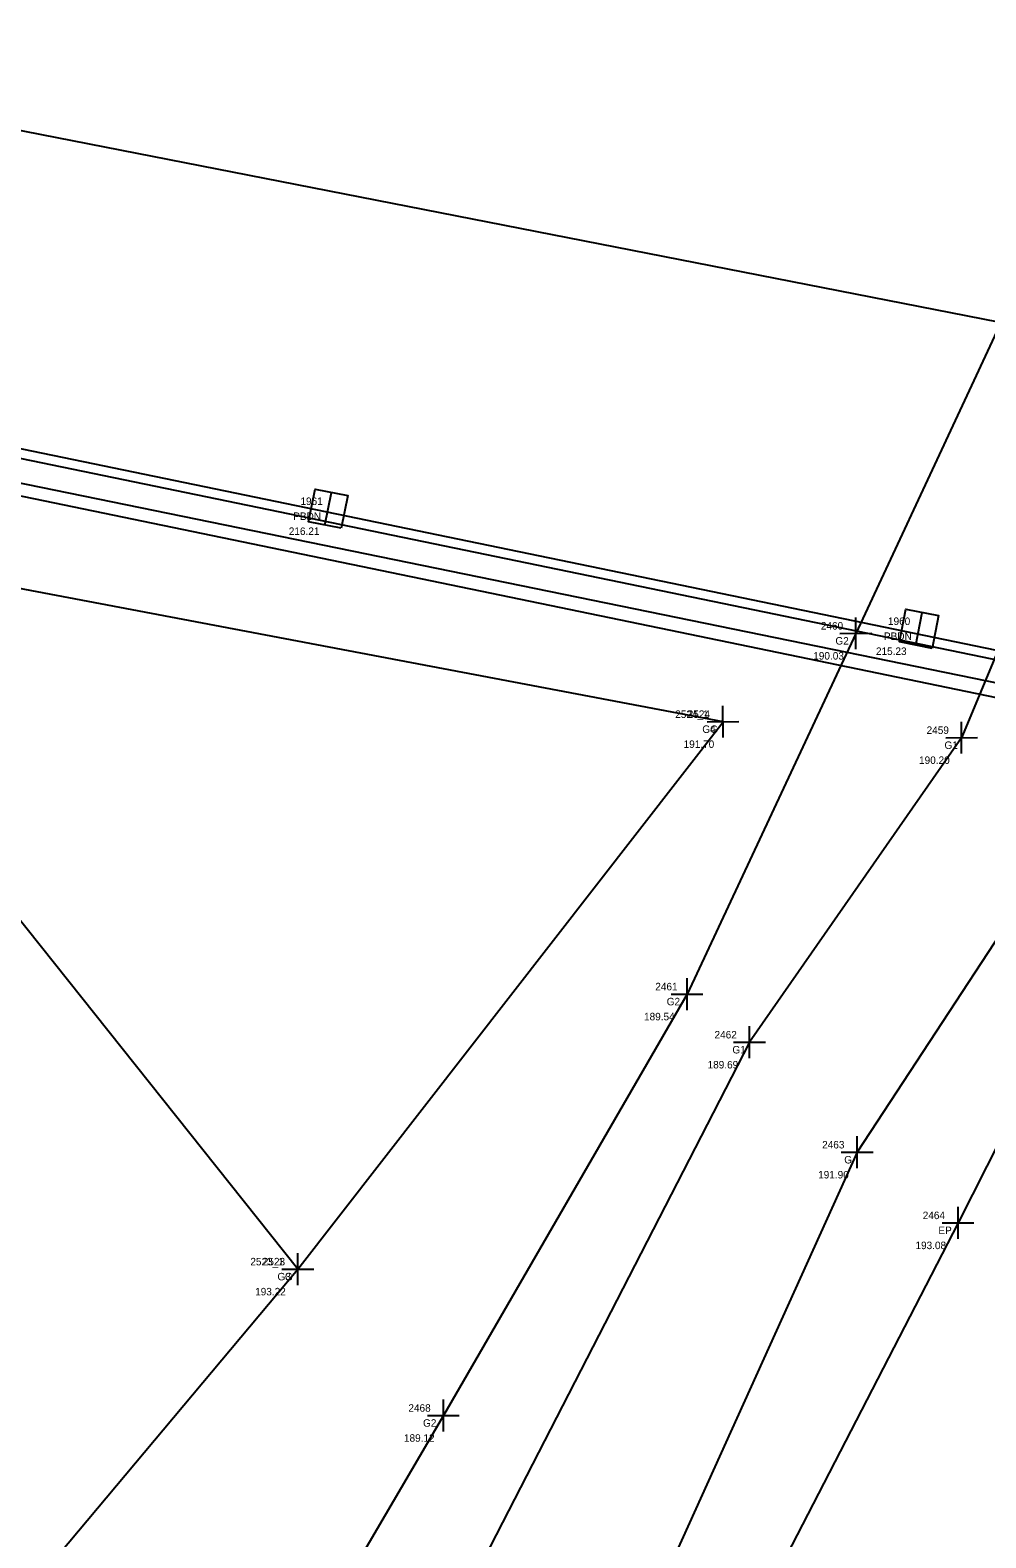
# Model space of a CAD drawing. Extents: x 1155460 to 1157069, y 590691 to 591363.
# Drawn here: x 1156326 to 1156364.2, y 591043.1 to 591103.4 of the extents above; entities that cross this region are included whole.
import ezdxf

# ---------------------------------------------------------------- set-up
doc = ezdxf.new("R2010")
doc.units = 0
for name, color, linetype in [('Default', 7, 'Continuous'), ('S_Bridge_Centerline', 7, 'Continuous'), ('S_Bridge_Curb', 7, 'Continuous'), ('S_Bridge_Deck', 7, 'Continuous'), ('S_Bridge_Downspout', 7, 'Continuous'), ('S_Bridge_Rail', 7, 'Continuous'), ('S_Field_Code', 7, 'Continuous'), ('S_Ground_Elevation', 7, 'Continuous'), ('S_Point_Elevation', 7, 'Continuous'), ('S_Point_Name', 7, 'Continuous'), ('S_Roadway_Edge_Pavement', 7, 'Continuous'), ('S_Survey_Shot', 7, 'Continuous')]:
    doc.layers.add(name, color=color, linetype=linetype)

msp = doc.modelspace()

# ---------------------------------------------------------------- linework, layer by layer
at = {"layer": 'Default'}
for p, q in [((1156337.9, 591084.266), (1156337.9, 591084.266)), ((1156361.542, 591079.466), (1156361.542, 591079.466))]:
    msp.add_line(p, q, dxfattribs=at)
at = {"layer": 'S_Bridge_Centerline'}
msp.add_lwpolyline([(1156315.508, 591101.371), (1156372.408, 591090.24), (1156431.554, 591078.114), (1156475.254, 591069.515)], dxfattribs=at)
at = {"layer": 'S_Bridge_Curb'}
for points in [[(1156309.461, 591089.603), (1156368.986, 591077.329), (1156424.735, 591065.932), (1156469.272, 591056.957)], [(1156468.917, 591055.972), (1156425.26, 591064.917), (1156366.557, 591076.907), (1156308.862, 591088.698)]]:
    msp.add_lwpolyline(points, dxfattribs=at)
at = {"layer": 'S_Bridge_Deck'}
msp.add_lwpolyline([(1156321.636, 591113.83), (1156379.075, 591102.191), (1156438.058, 591090.105), (1156481.699, 591081.221), (1156469.523, 591057.135), (1156425.816, 591065.905), (1156367.048, 591078.105), (1156309.431, 591089.995)], close=True, dxfattribs=at)
at = {"layer": 'S_Bridge_Downspout'}
for p, q in [((1156337.769, 591083.612), (1156338.031, 591084.92)), ((1156361.411, 591078.812), (1156361.672, 591080.119))]:
    msp.add_line(p, q, dxfattribs=at)
for points in [[(1156338.423, 591083.482), (1156337.116, 591083.743), (1156337.377, 591085.05), (1156338.684, 591084.789)], [(1156362.065, 591078.681), (1156360.757, 591078.942), (1156361.019, 591080.25), (1156362.326, 591079.989)]]:
    msp.add_lwpolyline(points, close=True, dxfattribs=at)
at = {"layer": 'S_Bridge_Rail'}
msp.add_lwpolyline([(1156468.705, 591055.401), (1156424.96, 591064.338), (1156366.256, 591076.365), (1156308.616, 591088.276)], dxfattribs=at)
at = {"layer": 'S_Ground_Elevation'}
for points in [[(1156379.906, 591125.75), (1156371.781, 591106.643), (1156359.013, 591079.281), (1156352.261, 591064.852), (1156342.509, 591047.996), (1156330.29, 591027.131), (1156317.384, 591002.477), (1156294.819, 590961.074), (1156271.751, 590921.229), (1156243.933, 590875.1), (1156220.497, 590838.098), (1156207.923, 590811.33), (1156193.803, 590789.379), (1156193.142, 590778.687)], [(1156384.307, 591123.72), (1156373.986, 591100.844), (1156363.249, 591075.107), (1156354.761, 591062.927), (1156343.414, 591040.885), (1156332.061, 591024.769), (1156321.368, 591002.613), (1156298.102, 590959.872), (1156275.04, 590917.944), (1156250.506, 590874.056), (1156227.624, 590835.562), (1156214.155, 590811.849), (1156201.099, 590789.179), (1156193.142, 590778.687), (1156176.179, 590756.924), (1156172.203, 590742.083)], [(1156390.175, 591120.033), (1156381.064, 591097.503), (1156368.236, 591072.501), (1156359.068, 591058.527), (1156343.042, 591023.13), (1156324.748, 590989.953), (1156305.968, 590954.129), (1156282.703, 590914.702), (1156259.469, 590868.947), (1156237.124, 590831.411), (1156221.354, 590804.624), (1156218.597, 590799.82), (1156211.828, 590795.443), (1156202.716, 590779.447), (1156183.916, 590752.585), (1156173.73, 590734.078)], [(1156353.701, 591075.748), (1156312.515, 591083.537), (1156308.901, 591085.521)], [(1156336.683, 591053.85), (1156319.901, 591074.903), (1156305.515, 591083.097), (1156299.714, 591084.96)], [(1156326.731, 591041.979), (1156336.683, 591053.85), (1156353.701, 591075.748)]]:
    msp.add_lwpolyline(points, dxfattribs=at)
at = {"layer": 'S_Roadway_Edge_Pavement'}
msp.add_lwpolyline([(1156394.452, 591118.152), (1156383.412, 591096.564), (1156371.167, 591071.625), (1156363.107, 591055.7), (1156344.853, 591020.331), (1156327.93, 590987.905), (1156310.138, 590952.311), (1156288.382, 590911.132), (1156264.007, 590866.376), (1156251.804, 590843.99), (1156242.045, 590830.497), (1156229.687, 590815.055), (1156224.596, 590802.999), (1156214.609, 590779.786), (1156200.016, 590742.951), (1156189.63, 590722.324)], dxfattribs=at)
at = {"layer": 'S_Survey_Shot'}
for p, q in [((1156359.015, 591078.645), (1156359.012, 591079.918)), ((1156358.377, 591079.28), (1156359.65, 591079.283)), ((1156359.013, 591079.281), (1156359.013, 591079.281)), ((1156353.702, 591075.112), (1156353.699, 591076.384)), ((1156353.702, 591075.112), (1156353.699, 591076.384)), ((1156353.064, 591075.747), (1156354.337, 591075.749)), ((1156353.064, 591075.747), (1156354.337, 591075.749)), ((1156353.701, 591075.748), (1156353.701, 591075.748)), ((1156353.701, 591075.748), (1156353.701, 591075.748)), ((1156363.25, 591074.471), (1156363.247, 591075.743)), ((1156362.612, 591075.106), (1156363.885, 591075.109)), ((1156363.249, 591075.107), (1156363.249, 591075.107)), ((1156352.262, 591064.215), (1156352.26, 591065.488)), ((1156351.625, 591064.85), (1156352.897, 591064.853)), ((1156352.261, 591064.852), (1156352.261, 591064.852)), ((1156354.762, 591062.29), (1156354.76, 591063.563)), ((1156354.125, 591062.925), (1156355.397, 591062.928)), ((1156354.761, 591062.927), (1156354.761, 591062.927)), ((1156359.069, 591057.891), (1156359.067, 591059.163)), ((1156358.432, 591058.525), (1156359.704, 591058.528)), ((1156359.068, 591058.527), (1156359.068, 591058.527)), ((1156363.108, 591055.063), (1156363.105, 591056.336)), ((1156362.47, 591055.698), (1156363.743, 591055.701)), ((1156363.107, 591055.7), (1156363.107, 591055.7)), ((1156336.684, 591053.214), (1156336.681, 591054.486)), ((1156336.684, 591053.214), (1156336.681, 591054.486)), ((1156336.046, 591053.849), (1156337.319, 591053.851)), ((1156336.046, 591053.849), (1156337.319, 591053.851)), ((1156336.683, 591053.85), (1156336.683, 591053.85)), ((1156336.683, 591053.85), (1156336.683, 591053.85)), ((1156342.51, 591047.36), (1156342.508, 591048.632)), ((1156341.873, 591047.994), (1156343.145, 591047.997)), ((1156342.509, 591047.996), (1156342.509, 591047.996))]:
    msp.add_line(p, q, dxfattribs=at)

# ---------------------------------------------------------------- texts
at = {"layer": 'S_Field_Code'}
for s, p in [('PBDN', (1156336.499, 591083.816)), ('PBDN', (1156360.141, 591079.016)), ('G2', (1156358.198, 591078.831)), ('G4', (1156352.871, 591075.298)), ('G', (1156353.186, 591075.298)), ('G1', (1156362.564, 591074.657)), ('G2', (1156351.446, 591064.402)), ('G1', (1156354.076, 591062.477)), ('G', (1156358.553, 591058.077)), ('EP', (1156362.32, 591055.25)), ('G3', (1156335.868, 591053.4)), ('G', (1156336.168, 591053.4)), ('G2', (1156341.694, 591047.546))]:
    msp.add_text(s, height=0.3, dxfattribs=at).set_placement(p)
at = {"layer": 'S_Point_Elevation'}
for s, p in [('216.21', (1156336.322, 591083.216)), ('215.23', (1156359.82, 591078.416)), ('190.03', (1156357.311, 591078.231)), ('191.70', (1156352.123, 591074.698)), ('191.70', (1156352.123, 591074.698)), ('190.20', (1156361.546, 591074.057)), ('189.54', (1156350.539, 591063.802)), ('189.69', (1156353.082, 591061.877)), ('191.90', (1156357.507, 591057.477)), ('193.08', (1156361.402, 591054.65)), ('193.22', (1156334.975, 591052.8)), ('193.22', (1156334.975, 591052.8)), ('189.12', (1156340.931, 591046.946))]:
    msp.add_text(s, height=0.3, dxfattribs=at).set_placement(p)
at = {"layer": 'S_Point_Name'}
for s, p in [('1961', (1156336.788, 591084.416)), ('1960', (1156360.302, 591079.616)), ('2460', (1156357.615, 591079.431)), ('2524_1', (1156351.787, 591075.898)), ('2524', (1156352.286, 591075.898)), ('2459', (1156361.848, 591075.257)), ('2461', (1156350.99, 591065.002)), ('2462', (1156353.36, 591063.077)), ('2463', (1156357.667, 591058.677)), ('2464', (1156361.692, 591055.85)), ('2523_1', (1156334.783, 591054)), ('2523', (1156335.282, 591054)), ('2468', (1156341.108, 591048.146))]:
    msp.add_text(s, height=0.3, dxfattribs=at).set_placement(p)

doc.saveas('drawing.dxf')
